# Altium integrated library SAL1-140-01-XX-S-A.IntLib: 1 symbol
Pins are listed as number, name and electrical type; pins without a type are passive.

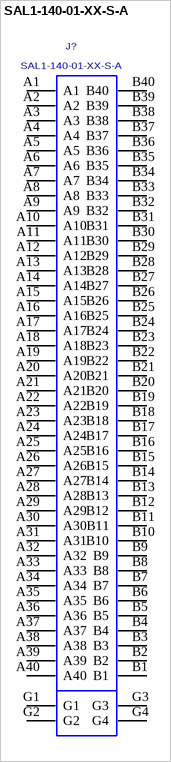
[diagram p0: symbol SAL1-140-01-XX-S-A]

## SAL1-140-01-XX-S-A
designator J?
1MM SERIAL ATA LINK CONNECTOR.; MANUFACTURER: SAMTEC
footprint SAL1-140-01-XX-S-A
pins: A1, A2, A3, A4, A5, A6, A7, A8, A9, A10, A11, A12, A13, A14, A15, A16, A17, A18, A19, A20, A21, A22, A23, A24, A25, A26, A27, A28, A29, A30, A31, A32, A33, A34, A35, A36, A37, A38, A39, A40, B1, B2, B3, B4, B5, B6, B7, B8, B9, B10, B11, B12, B13, B14, B15, B16, B17, B18, B19, B20, B21, B22, B23, B24, B25, B26, B27, B28, B29, B30, B31, B32, B33, B34, B35, B36, B37, B38, B39, B40, G1, G2, G3, G4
